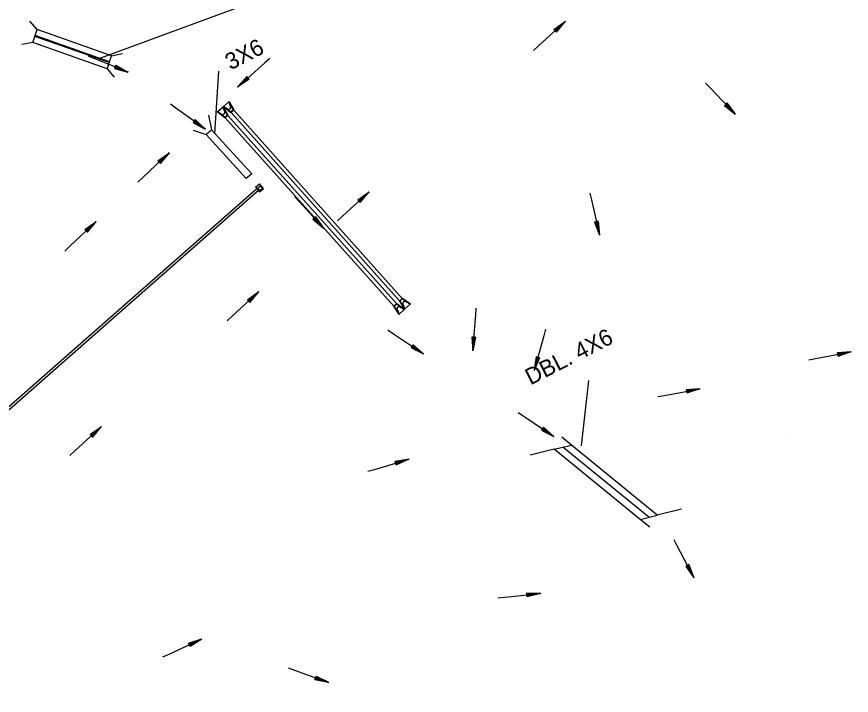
# Model space of a CAD drawing. Extents: x 1308292 to 1312792, y 238563 to 242743.
# Drawn here: x 1309874 to 1310582, y 240039 to 240614 of the extents above; entities that cross this region are included whole.
import ezdxf

# ---------------------------------------------------------------- set-up
doc = ezdxf.new("R2010")
doc.units = 0
for name, color, linetype in [('R_Box Culvert', 7, 'Continuous'), ('R_BRIDGE OLD', 7, 'Continuous'), ('R_Drop Inlet', 7, 'Continuous'), ('R_FES', 7, 'Continuous'), ('R_Flow Arrows', 7, 'Continuous'), ('R_Pipe Culvert', 7, 'Continuous')]:
    doc.layers.add(name, color=color, linetype=linetype)

msp = doc.modelspace()

# ---------------------------------------------------------------- linework, layer by layer
at = {"layer": 'R_Box Culvert'}
for p, q in [((1309891.91, 240602.96), (1309885.73, 240610.18)), ((1309888.04, 240591.96), (1309891.91, 240602.96)), ((1309954.9, 240580.8), (1309891.91, 240602.96)), ((1309952.86, 240574.98), (1309889.87, 240597.15)), ((1309953.08, 240575.61), (1309890.09, 240597.78)), ((1309888.04, 240591.96), (1309878.7, 240590.21)), ((1309951.03, 240569.8), (1309888.04, 240591.96)), ((1309951.03, 240569.8), (1309954.9, 240580.8)), ((1309954.9, 240580.8), (1309964.24, 240582.55)), ((1309951.03, 240569.8), (1309957.21, 240562.59)), ((1310037, 240530.3), (1310039.69, 240517.97)), ((1310023.94, 240517.61), (1310035.17, 240514.02)), ((1310039.69, 240517.97), (1310073.68, 240480.6)), ((1310035.17, 240514.02), (1310069.02, 240476.81)), ((1310344.73, 240250.8), (1310336.6, 240257.44)), ((1310530.24, 240257.6), (1310530.24, 240257.6)), ((1310530.24, 240257.6), (1310530.24, 240257.6)), ((1310530.24, 240257.6), (1310530.24, 240257.6)), ((1310330.14, 240247.22), (1310309.74, 240242.23)), ((1310330.14, 240247.22), (1310344.73, 240250.8)), ((1310402.87, 240187.81), (1310330.14, 240247.22)), ((1310410.17, 240189.6), (1310337.44, 240249.01)), ((1310417.46, 240191.39), (1310344.73, 240250.8)), ((1310402.87, 240187.81), (1310417.46, 240191.39)), ((1310437.86, 240196.38), (1310417.46, 240191.39)), ((1310411, 240181.17), (1310402.87, 240187.81))]:
    msp.add_line(p, q, dxfattribs=at)
msp.add_arc((1309056.38, 241637.96), 1490.39, 311.05133, 311.28203, dxfattribs=at)
at = {"layer": 'R_BRIDGE OLD'}
for p, q in [((1309945.82, 240579.12), (1310063.23, 240622.23)), ((1310042.33, 240514.66), (1310045.86, 240567.79)), ((1310353.17, 240250.13), (1310359.53, 240305.53))]:
    msp.add_line(p, q, dxfattribs=at)
at = {"layer": 'R_Drop Inlet'}
for p, q in [((1310076.91, 240469.43), (1310080.17, 240472.28)), ((1310076.91, 240469.43), (1310080.37, 240465.47)), ((1310080.98, 240470.34), (1310078.73, 240468.36)), ((1310078.73, 240468.36), (1310080.44, 240466.41)), ((1310083.63, 240468.33), (1310080.17, 240472.28)), ((1310080.37, 240465.47), (1310083.63, 240468.33)), ((1310080.44, 240466.41), (1310082.69, 240468.39)), ((1310082.69, 240468.39), (1310080.98, 240470.34))]:
    msp.add_line(p, q, dxfattribs=at)
at = {"layer": 'R_FES'}
for p, q in [((1310044.44, 240533.2), (1310049.46, 240537.59)), ((1310050.78, 240533.23), (1310049.2, 240537.36)), ((1310053.28, 240530.5), (1310049.2, 240537.36)), ((1310049.46, 240537.59), (1310054.48, 240541.97)), ((1310053.69, 240530.47), (1310049.46, 240537.59)), ((1310049.46, 240537.59), (1310050.78, 240533.23)), ((1310055.95, 240532.44), (1310049.46, 240537.59)), ((1310053.62, 240535.47), (1310049.46, 240537.59)), ((1310049.71, 240537.81), (1310053.62, 240535.47)), ((1310055.97, 240532.85), (1310049.71, 240537.81)), ((1310055.8, 240537.62), (1310054.22, 240541.75)), ((1310058.3, 240534.89), (1310054.22, 240541.75)), ((1310058.71, 240534.85), (1310054.48, 240541.97)), ((1310054.48, 240541.97), (1310055.8, 240537.62)), ((1310050.93, 240528.05), (1310044.44, 240533.2)), ((1310048.6, 240531.08), (1310044.44, 240533.2)), ((1310044.69, 240533.42), (1310048.6, 240531.08)), ((1310050.95, 240528.46), (1310044.69, 240533.42)), ((1310053.69, 240530.47), (1310050.93, 240528.05)), ((1310053.28, 240530.5), (1310050.95, 240528.46)), ((1310053.28, 240530.5), (1310053.69, 240530.47)), ((1310058.71, 240534.85), (1310055.95, 240532.44)), ((1310055.97, 240532.85), (1310055.95, 240532.44)), ((1310058.3, 240534.89), (1310055.97, 240532.85)), ((1310058.3, 240534.89), (1310058.71, 240534.85)), ((1310050.95, 240528.46), (1310050.93, 240528.05)), ((1310198.81, 240372.88), (1310201.51, 240375.36)), ((1310199.22, 240372.86), (1310201.5, 240374.95)), ((1310201.5, 240374.95), (1310201.51, 240375.36)), ((1310201.5, 240374.95), (1310207.88, 240370.15)), ((1310201.51, 240375.36), (1310208.13, 240370.38)), ((1310193.9, 240368.37), (1310196.6, 240370.85)), ((1310193.9, 240368.37), (1310198.31, 240361.36)), ((1310194.31, 240368.35), (1310193.9, 240368.37)), ((1310194.31, 240368.35), (1310196.59, 240370.44)), ((1310194.31, 240368.35), (1310198.56, 240361.59)), ((1310196.59, 240370.44), (1310196.6, 240370.85)), ((1310196.59, 240370.44), (1310202.97, 240365.64)), ((1310196.6, 240370.85), (1310203.22, 240365.87)), ((1310198.81, 240372.88), (1310203.22, 240365.87)), ((1310199.22, 240372.86), (1310198.81, 240372.88)), ((1310199, 240367.88), (1310203.22, 240365.87)), ((1310202.97, 240365.64), (1310199, 240367.88)), ((1310199.22, 240372.86), (1310203.47, 240366.1)), ((1310201.79, 240370.19), (1310203.47, 240366.1)), ((1310203.22, 240365.87), (1310201.79, 240370.19)), ((1310208.13, 240370.38), (1310203.22, 240365.87)), ((1310203.91, 240372.39), (1310208.13, 240370.38)), ((1310207.88, 240370.15), (1310203.91, 240372.39)), ((1310196.88, 240365.68), (1310198.56, 240361.59)), ((1310198.31, 240361.36), (1310196.88, 240365.68)), ((1310203.22, 240365.87), (1310198.31, 240361.36))]:
    msp.add_line(p, q, dxfattribs=at)
for centre, start, end in [((1310054.25, 240537.01), 247.86326, 21.39399), ((1310049.23, 240532.63), 247.86326, 21.39399), ((1310198.41, 240366.32), 69.28488, 202.81562), ((1310203.32, 240370.83), 69.28488, 202.81562)]:
    msp.add_arc(centre, 1.67, start, end, dxfattribs=at)
at = {"layer": 'R_Flow Arrows'}
for p, q in [((1310329.84, 240603.11), (1310339.52, 240609.93)), ((1310331.89, 240600.87), (1310339.52, 240609.93)), ((1310329.84, 240603.11), (1310331.89, 240600.87)), ((1309958.5, 240572.84), (1309957.33, 240570.03)), ((1309958.5, 240572.84), (1309968.77, 240566.94)), ((1309957.33, 240570.03), (1309968.77, 240566.94)), ((1310069.54, 240563.1), (1310061.75, 240554.19)), ((1310071.56, 240560.83), (1310061.75, 240554.19)), ((1310071.56, 240560.83), (1310069.54, 240563.1)), ((1310476.51, 240540.75), (1310474.32, 240538.64)), ((1310474.32, 240538.64), (1310483.58, 240531.25)), ((1310476.51, 240540.75), (1310483.58, 240531.25)), ((1310025.76, 240526.74), (1310023.95, 240524.3)), ((1310023.95, 240524.3), (1310034.31, 240518.55)), ((1310025.76, 240526.74), (1310034.31, 240518.55)), ((1309994.2, 240491.71), (1310003.85, 240498.57)), ((1309996.26, 240489.47), (1310003.85, 240498.57)), ((1309994.2, 240491.71), (1309996.26, 240489.47)), ((1310163.56, 240458.63), (1310173.25, 240465.46)), ((1310165.62, 240456.39), (1310173.25, 240465.46)), ((1310163.56, 240458.63), (1310165.62, 240456.39)), ((1310127.67, 240444.33), (1310125.43, 240442.28)), ((1310127.67, 240444.33), (1310134.47, 240434.63)), ((1309932.29, 240433.35), (1309941.95, 240440.21)), ((1309934.36, 240431.12), (1309941.95, 240440.21)), ((1310125.43, 240442.28), (1310134.47, 240434.63)), ((1310367.29, 240440.42), (1310364.33, 240439.72)), ((1310364.33, 240439.72), (1310368.51, 240428.63)), ((1310367.29, 240440.42), (1310368.51, 240428.63)), ((1309932.29, 240433.35), (1309934.36, 240431.12)), ((1310069.99, 240373.99), (1310079.67, 240380.81)), ((1310072.04, 240371.75), (1310079.67, 240380.81)), ((1310069.99, 240373.99), (1310072.04, 240371.75)), ((1310260.3, 240342.36), (1310261.05, 240330.53)), ((1310263.33, 240342.16), (1310260.3, 240342.36)), ((1310263.33, 240342.16), (1310261.05, 240330.53)), ((1310210.42, 240335.86), (1310208.73, 240333.34)), ((1310208.73, 240333.34), (1310219.34, 240328.06)), ((1310210.42, 240335.86), (1310219.34, 240328.06)), ((1310314.71, 240325.58), (1310313.12, 240313.84)), ((1310317.64, 240324.79), (1310313.12, 240313.84)), ((1310317.64, 240324.79), (1310314.71, 240325.58)), ((1310570.06, 240329.2), (1310581.88, 240329.97)), ((1310570.06, 240329.2), (1310570.65, 240326.21)), ((1310570.65, 240326.21), (1310581.88, 240329.97)), ((1310442.04, 240297.91), (1310453.87, 240298.69)), ((1310442.04, 240297.91), (1310442.63, 240294.93)), ((1310442.63, 240294.93), (1310453.87, 240298.69)), ((1309936.6, 240259.72), (1309946.28, 240266.54)), ((1309938.66, 240257.48), (1309946.28, 240266.54)), ((1310320.99, 240265.83), (1310319.28, 240263.32)), ((1310319.28, 240263.32), (1310329.85, 240257.98)), ((1310320.99, 240265.83), (1310329.85, 240257.98)), ((1309936.6, 240259.72), (1309938.66, 240257.48)), ((1310195.35, 240237.01), (1310207.03, 240239.01)), ((1310196.25, 240234.1), (1310207.03, 240239.01)), ((1310196.25, 240234.1), (1310195.35, 240237.01)), ((1310444.24, 240149.44), (1310441.55, 240148.02)), ((1310441.55, 240148.02), (1310448.37, 240138.34)), ((1310444.24, 240149.44), (1310448.37, 240138.34)), ((1310306.83, 240125.4), (1310318.68, 240125.22)), ((1310307.18, 240122.38), (1310306.83, 240125.4)), ((1310307.18, 240122.38), (1310318.68, 240125.22)), ((1310020.16, 240083), (1310031.44, 240086.63)), ((1310021.46, 240080.25), (1310031.44, 240086.63)), ((1310021.46, 240080.25), (1310020.16, 240083)), ((1310127.25, 240052.17), (1310128.24, 240055.04)), ((1310128.24, 240055.04), (1310138.85, 240049.78)), ((1310127.25, 240052.17), (1310138.85, 240049.78))]:
    msp.add_line(p, q, dxfattribs=at)
for points in [[(1310312.65, 240585.25), (1310316.88, 240589.16), (1310339.52, 240609.93)], [(1310330.45, 240602.44), (1310335.03, 240606.64), (1310335.65, 240607.2)], [(1310330.66, 240602.21), (1310335.24, 240606.42), (1310337.59, 240608.56)], [(1310331.07, 240601.76), (1310335.65, 240605.97), (1310338, 240608.11)], [(1310330.04, 240602.88), (1310331.77, 240604.47)], [(1310330.25, 240602.66), (1310333.71, 240605.84)], [(1310331.28, 240601.54), (1310335.86, 240605.74), (1310336.47, 240606.31)], [(1310331.48, 240601.32), (1310334.94, 240604.49)], [(1310331.69, 240601.09), (1310333.42, 240602.68)], [(1309934.96, 240580.66), (1309940.31, 240578.53), (1309968.83, 240567.09)], [(1310088.93, 240578.53), (1310084.66, 240574.65), (1310061.85, 240554.07)], [(1309958.03, 240571.71), (1309963.78, 240569.34), (1309966.71, 240568.11)], [(1309958.15, 240572), (1309963.89, 240569.62), (1309964.66, 240569.3)], [(1309958.26, 240572.28), (1309962.61, 240570.48)], [(1309958.38, 240572.56), (1309960.55, 240571.66)], [(1309957.45, 240570.31), (1309959.62, 240569.41)], [(1309957.57, 240570.59), (1309961.91, 240568.79)], [(1309957.68, 240570.87), (1309963.43, 240568.5), (1309964.19, 240568.18)], [(1309957.8, 240571.15), (1309963.54, 240568.78), (1309966.48, 240567.55)], [(1310070.35, 240562.19), (1310065.69, 240558.08), (1310063.3, 240555.98)], [(1310070.75, 240561.74), (1310066.09, 240557.62), (1310063.7, 240555.52)], [(1310070.15, 240562.42), (1310065.49, 240558.31), (1310064.86, 240557.76)], [(1310070.95, 240561.51), (1310066.29, 240557.39), (1310065.67, 240556.84)], [(1310069.95, 240562.65), (1310066.42, 240559.54)], [(1310071.16, 240561.28), (1310067.63, 240558.17)], [(1310069.75, 240562.88), (1310067.98, 240561.32)], [(1310071.36, 240561.05), (1310069.59, 240559.5)], [(1310458.38, 240557.64), (1310462.35, 240553.46), (1310483.47, 240531.15)], [(1310004.79, 240540), (1310009.48, 240536.64), (1310034.4, 240518.67)], [(1310474.54, 240538.85), (1310476.17, 240537.16)], [(1310474.76, 240539.06), (1310478.02, 240535.68)], [(1310474.98, 240539.27), (1310479.3, 240534.8), (1310479.87, 240534.2)], [(1310475.19, 240539.49), (1310479.51, 240535.02), (1310481.72, 240532.72)], [(1310475.63, 240539.91), (1310479.95, 240535.44), (1310482.16, 240533.14)], [(1310475.85, 240540.12), (1310480.17, 240535.65), (1310480.75, 240535.05)], [(1310476.07, 240540.33), (1310479.34, 240536.95)], [(1310476.29, 240540.54), (1310477.92, 240538.85)], [(1310024.13, 240524.54), (1310026.02, 240523.15)], [(1310024.31, 240524.78), (1310028.1, 240522)], [(1310024.49, 240525.03), (1310029.5, 240521.34), (1310030.17, 240520.85)], [(1310024.67, 240525.27), (1310029.68, 240521.59), (1310032.23, 240519.69)], [(1310025.03, 240525.76), (1310030.04, 240522.08), (1310032.6, 240520.18)], [(1310025.21, 240526.01), (1310030.22, 240522.32), (1310030.89, 240521.82)], [(1310025.39, 240526.25), (1310029.18, 240523.47)], [(1310025.58, 240526.5), (1310027.47, 240525.1)], [(1309977.24, 240473.61), (1309981.41, 240477.58), (1310003.75, 240498.68)], [(1309994.61, 240491.26), (1309998.06, 240494.45)], [(1309994.82, 240491.04), (1309999.38, 240495.26), (1310000, 240495.82)], [(1309995.02, 240490.81), (1309999.59, 240495.04), (1310001.93, 240497.19)], [(1309995.44, 240490.37), (1310000, 240494.59), (1310002.34, 240496.74)], [(1309995.64, 240490.14), (1310000.21, 240494.36), (1310000.82, 240494.93)], [(1309994.4, 240491.48), (1309996.13, 240493.08)], [(1309995.85, 240489.92), (1309999.3, 240493.11)], [(1309996.06, 240489.7), (1309997.78, 240491.29)], [(1310146.37, 240440.77), (1310150.61, 240444.68), (1310173.25, 240465.46)], [(1310109.86, 240461.58), (1310113.76, 240457.33), (1310134.47, 240434.63)], [(1310163.77, 240458.41), (1310165.5, 240460)], [(1310163.97, 240458.19), (1310167.44, 240461.36)], [(1310164.18, 240457.96), (1310168.76, 240462.17), (1310169.38, 240462.73)], [(1310164.39, 240457.74), (1310168.97, 240461.94), (1310171.32, 240464.09)], [(1310164.8, 240457.29), (1310169.38, 240461.49), (1310171.73, 240463.64)], [(1310165, 240457.07), (1310169.58, 240461.27), (1310170.2, 240461.83)], [(1310165.21, 240456.84), (1310168.67, 240460.02)], [(1310165.41, 240456.62), (1310167.14, 240458.21)], [(1310360.34, 240464.19), (1310361.62, 240458.57), (1310368.37, 240428.6)], [(1310127.45, 240444.13), (1310129.03, 240442.39)], [(1309915.33, 240415.25), (1309919.51, 240419.22), (1309941.85, 240440.32)], [(1309932.91, 240432.68), (1309937.48, 240436.9), (1309938.09, 240437.47)], [(1309933.12, 240432.46), (1309937.68, 240436.68), (1309940.03, 240438.83)], [(1309933.53, 240432.01), (1309938.1, 240436.23), (1309940.44, 240438.38)], [(1310125.65, 240442.49), (1310127.23, 240440.75)], [(1310125.88, 240442.69), (1310129.04, 240439.22)], [(1310126.1, 240442.9), (1310130.29, 240438.3), (1310130.85, 240437.69)], [(1310126.32, 240443.1), (1310130.51, 240438.51), (1310132.65, 240436.15)], [(1310126.77, 240443.51), (1310130.96, 240438.92), (1310133.1, 240436.56)], [(1310127, 240443.72), (1310131.19, 240439.12), (1310131.75, 240438.5)], [(1310127.22, 240443.92), (1310130.39, 240440.45)], [(1310364.63, 240439.79), (1310365.17, 240437.5)], [(1310364.93, 240439.86), (1310366.01, 240435.28)], [(1310365.22, 240439.93), (1310366.65, 240433.88), (1310366.84, 240433.07)], [(1310365.52, 240440), (1310366.95, 240433.95), (1310367.67, 240430.85)], [(1310366.11, 240440.14), (1310367.54, 240434.08), (1310368.26, 240430.99)], [(1310366.41, 240440.21), (1310367.83, 240434.15), (1310368.02, 240433.34)], [(1310366.7, 240440.28), (1310367.78, 240435.7)], [(1310367, 240440.35), (1310367.54, 240438.06)], [(1309932.5, 240433.13), (1309934.23, 240434.72)], [(1309932.71, 240432.9), (1309936.16, 240436.09)], [(1309933.74, 240431.79), (1309938.3, 240436.01), (1309938.92, 240436.57)], [(1309933.95, 240431.56), (1309937.4, 240434.75)], [(1309934.15, 240431.34), (1309935.88, 240432.93)], [(1310052.8, 240356.12), (1310057.03, 240360.03), (1310079.67, 240380.81)], [(1310070.19, 240373.76), (1310071.92, 240375.35)], [(1310070.4, 240373.54), (1310073.86, 240376.72)], [(1310070.6, 240373.31), (1310075.18, 240377.52), (1310075.8, 240378.08)], [(1310070.81, 240373.09), (1310075.39, 240377.3), (1310077.74, 240379.44)], [(1310071.22, 240372.64), (1310075.8, 240376.85), (1310078.15, 240378.99)], [(1310071.42, 240372.42), (1310076, 240376.62), (1310076.62, 240377.18)], [(1310071.63, 240372.19), (1310075.09, 240375.37)], [(1310071.84, 240371.97), (1310073.57, 240373.56)], [(1310263.64, 240366.93), (1310263.22, 240361.18), (1310260.9, 240330.54)], [(1310189.01, 240348.35), (1310193.81, 240345.16), (1310219.34, 240328.06)], [(1310322.81, 240349.02), (1310321.27, 240343.46), (1310312.98, 240313.87)], [(1310260.6, 240342.34), (1310260.45, 240339.99)], [(1310260.91, 240342.32), (1310260.6, 240337.63)], [(1310261.21, 240342.3), (1310260.81, 240336.09), (1310260.75, 240335.26)], [(1310261.51, 240342.28), (1310261.11, 240336.07), (1310260.89, 240332.9)], [(1310262.12, 240342.24), (1310261.72, 240336.03), (1310261.5, 240332.86)], [(1310262.42, 240342.22), (1310262.02, 240336.01), (1310261.96, 240335.18)], [(1310262.73, 240342.2), (1310262.42, 240337.51)], [(1310263.03, 240342.18), (1310262.88, 240339.83)], [(1310208.9, 240333.59), (1310210.85, 240332.28)], [(1310209.07, 240333.84), (1310212.98, 240331.23)], [(1310209.24, 240334.09), (1310214.41, 240330.64), (1310215.1, 240330.17)], [(1310209.41, 240334.35), (1310214.58, 240330.89), (1310217.21, 240329.11)], [(1310209.75, 240334.85), (1310214.91, 240331.39), (1310217.55, 240329.62)], [(1310209.92, 240335.1), (1310215.08, 240331.65), (1310215.77, 240331.18)], [(1310210.09, 240335.36), (1310213.99, 240332.74)], [(1310210.25, 240335.61), (1310212.21, 240334.3)], [(1310315.88, 240325.26), (1310314.27, 240319.26), (1310313.43, 240316.19)], [(1310315.59, 240325.34), (1310313.97, 240319.34), (1310313.75, 240318.53)], [(1310316.47, 240325.1), (1310314.85, 240319.1), (1310314.02, 240316.03)], [(1310315.29, 240325.42), (1310314.07, 240320.88)], [(1310315, 240325.5), (1310314.39, 240323.23)], [(1310316.76, 240325.02), (1310315.15, 240319.02), (1310314.93, 240318.21)], [(1310317.06, 240324.94), (1310315.83, 240320.41)], [(1310317.35, 240324.86), (1310316.74, 240322.6)], [(1310546.04, 240323.14), (1310551.7, 240324.21), (1310581.91, 240329.83)], [(1310570.12, 240328.9), (1310572.43, 240329.35)], [(1310570.18, 240328.6), (1310574.79, 240329.51)], [(1310570.24, 240328.3), (1310576.34, 240329.5), (1310577.16, 240329.66)], [(1310570.3, 240328), (1310576.4, 240329.2), (1310579.52, 240329.81)], [(1310570.41, 240327.41), (1310576.51, 240328.61), (1310579.64, 240329.21)], [(1310570.47, 240327.11), (1310576.57, 240328.31), (1310577.39, 240328.47)], [(1310570.53, 240326.81), (1310575.14, 240327.72)], [(1310570.59, 240326.51), (1310572.9, 240326.96)], [(1310418.02, 240291.85), (1310423.69, 240292.92), (1310453.89, 240298.54)], [(1310442.1, 240297.61), (1310444.41, 240298.07)], [(1310442.16, 240297.31), (1310446.77, 240298.22)], [(1310442.22, 240297.02), (1310448.32, 240298.22), (1310449.14, 240298.38)], [(1310442.28, 240296.72), (1310448.38, 240297.92), (1310451.5, 240298.52)], [(1310442.4, 240296.12), (1310448.5, 240297.32), (1310451.62, 240297.93)], [(1310442.46, 240295.82), (1310448.56, 240297.02), (1310449.37, 240297.18)], [(1310442.51, 240295.52), (1310447.13, 240296.43)], [(1310442.57, 240295.23), (1310444.88, 240295.68)], [(1310299.65, 240278.46), (1310304.43, 240275.24), (1310329.85, 240257.98)], [(1309919.41, 240241.86), (1309923.65, 240245.77), (1309946.28, 240266.54)], [(1309936.81, 240259.5), (1309938.54, 240261.08)], [(1309937.01, 240259.27), (1309940.47, 240262.45)], [(1309937.22, 240259.05), (1309941.8, 240263.25), (1309942.41, 240263.81)], [(1309937.42, 240258.82), (1309942, 240263.03), (1309944.35, 240265.17)], [(1309937.83, 240258.38), (1309942.41, 240262.58), (1309944.76, 240264.72)], [(1309938.04, 240258.15), (1309942.62, 240262.35), (1309943.23, 240262.92)], [(1309938.25, 240257.93), (1309941.71, 240261.11)], [(1310319.45, 240263.57), (1310321.39, 240262.25)], [(1310319.62, 240263.82), (1310323.51, 240261.18)], [(1310319.79, 240264.07), (1310324.94, 240260.58), (1310325.62, 240260.11)], [(1310319.96, 240264.33), (1310325.11, 240260.83), (1310327.73, 240259.04)], [(1310320.3, 240264.83), (1310325.45, 240261.34), (1310328.08, 240259.54)], [(1310320.47, 240265.08), (1310325.62, 240261.59), (1310326.31, 240261.12)], [(1310320.65, 240265.33), (1310324.53, 240262.69)], [(1310320.82, 240265.58), (1310322.76, 240264.26)], [(1309938.45, 240257.7), (1309940.18, 240259.29)], [(1310172.08, 240228.52), (1310177.61, 240230.14), (1310207.07, 240238.86)], [(1310195.44, 240236.72), (1310197.69, 240237.41)], [(1310195.53, 240236.43), (1310200.02, 240237.81)], [(1310195.62, 240236.14), (1310201.56, 240237.97), (1310202.36, 240238.21)], [(1310195.71, 240235.85), (1310201.65, 240237.67), (1310204.69, 240238.62)], [(1310195.89, 240235.27), (1310201.83, 240237.09), (1310204.87, 240238.04)], [(1310195.98, 240234.98), (1310201.92, 240236.8), (1310202.72, 240237.05)], [(1310196.07, 240234.68), (1310200.56, 240236.07)], [(1310196.16, 240234.39), (1310198.4, 240235.08)], [(1310431.35, 240170.61), (1310434.05, 240165.52), (1310448.37, 240138.34)], [(1310441.82, 240148.16), (1310442.92, 240146.08)], [(1310442.09, 240148.31), (1310444.28, 240144.15)], [(1310442.36, 240148.45), (1310445.26, 240142.95), (1310445.64, 240142.21)], [(1310442.63, 240148.59), (1310445.53, 240143.09), (1310447, 240140.27)], [(1310443.17, 240148.87), (1310446.07, 240143.37), (1310447.54, 240140.55)], [(1310443.44, 240149.01), (1310446.33, 240143.51), (1310446.72, 240142.77)], [(1310443.71, 240149.16), (1310445.9, 240145)], [(1310443.97, 240149.3), (1310445.07, 240147.22)], [(1310282.4, 240121.33), (1310288.13, 240121.9), (1310318.7, 240125.06)], [(1310306.87, 240125.1), (1310309.2, 240125.36)], [(1310306.9, 240124.79), (1310311.57, 240125.33)], [(1310306.94, 240124.49), (1310313.11, 240125.2), (1310313.94, 240125.29)], [(1310306.97, 240124.19), (1310313.15, 240124.89), (1310316.31, 240125.26)], [(1310307.04, 240123.58), (1310313.22, 240124.29), (1310316.38, 240124.66)], [(1310307.08, 240123.28), (1310313.25, 240123.99), (1310314.08, 240124.08)], [(1310307.11, 240122.98), (1310311.78, 240123.51)], [(1310307.14, 240122.68), (1310309.48, 240122.94)], [(1309998.32, 240071.31), (1310003.57, 240073.69), (1310031.5, 240086.49)], [(1310020.29, 240082.72), (1310022.42, 240083.73)], [(1310020.42, 240082.45), (1310024.67, 240084.45)], [(1310020.55, 240082.17), (1310026.17, 240084.82), (1310026.92, 240085.18)], [(1310020.68, 240081.9), (1310026.3, 240084.55), (1310029.18, 240085.91)], [(1310020.94, 240081.35), (1310026.56, 240084), (1310029.44, 240085.36)], [(1310021.07, 240081.07), (1310026.69, 240083.72), (1310027.45, 240084.08)], [(1310021.2, 240080.8), (1310025.45, 240082.8)], [(1310021.33, 240080.52), (1310023.45, 240081.52)], [(1310104.43, 240061.88), (1310109.86, 240059.93), (1310138.8, 240049.64)], [(1310127.35, 240052.45), (1310129.57, 240051.69)], [(1310127.45, 240052.74), (1310131.89, 240051.21)], [(1310127.55, 240053.03), (1310133.43, 240051.01), (1310134.22, 240050.74)], [(1310127.65, 240053.32), (1310133.53, 240051.29), (1310136.54, 240050.27)], [(1310127.84, 240053.89), (1310133.72, 240051.87), (1310136.73, 240050.84)], [(1310127.94, 240054.18), (1310133.82, 240052.16), (1310134.61, 240051.89)], [(1310128.04, 240054.47), (1310132.49, 240052.94)], [(1310128.14, 240054.75), (1310130.36, 240053.99)]]:
    msp.add_lwpolyline(points, dxfattribs=at)
at = {"layer": 'R_Pipe Culvert'}
for p, q in [((1310196.36, 240370.63), (1310053.44, 240530.25)), ((1310199.06, 240373.11), (1310056.2, 240532.66)), ((1310201.27, 240375.14), (1310058.46, 240534.64)), ((1310194.15, 240368.6), (1310051.18, 240528.27)), ((1310073.68, 240480.6), (1310069.02, 240476.81)), ((1309590.57, 240040.19), (1310077.98, 240468.2)), ((1309591.88, 240038.68), (1310079.3, 240466.69))]:
    msp.add_line(p, q, dxfattribs=at)

# ---------------------------------------------------------------- texts
at = {"layer": 'R_BRIDGE OLD'}
for s, p in [('3X6', (1310055.7, 240568.29)), ('DBL. 4X6', (1310309.97, 240301.26))]:
    msp.add_text(s, height=14, rotation=27.13195, dxfattribs=at).set_placement(p)

doc.saveas('drawing.dxf')
